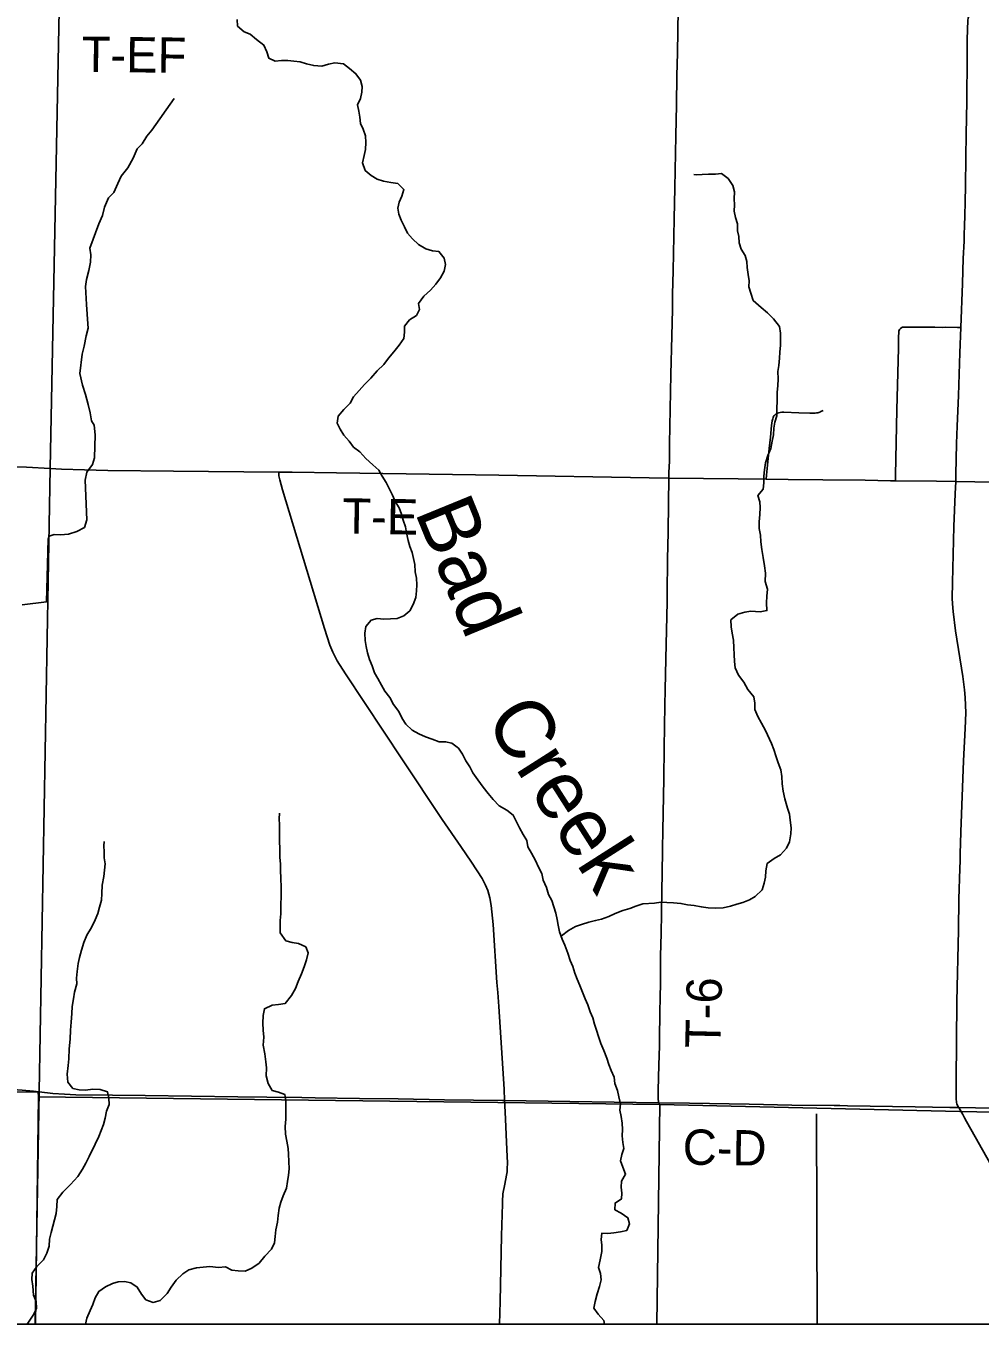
# Model space of a CAD drawing. Extents: x -21.7 to 34, y 0 to 22.
# Drawn here: x 27.584 to 29.12, y 14.1 to 16.19 of the extents above; entities that cross this region are included whole.
import ezdxf

# ---------------------------------------------------------------- set-up
doc = ezdxf.new("R2010")
doc.units = 0
for name, color, linetype in [('Default', 7, 'Continuous'), ('GM_X_County_Road', 7, 'Continuous'), ('GM_X_County_Road_Text', 7, 'Continuous'), ('GM_X_Interchange_Ramps', 7, 'Continuous'), ('GM_X_Minor_River', 7, 'Continuous'), ('GM_X_Minor_River_Text', 7, 'Continuous'), ('GM_X_Township_Road', 7, 'Continuous'), ('GM_X_Township_Road_Text', 7, 'Continuous'), ('SH_Data', 7, 'Continuous')]:
    doc.layers.add(name, color=color, linetype=linetype)

msp = doc.modelspace()

# ---------------------------------------------------------------- linework, layer by layer
at = {"layer": 'Default'}
for points in [[(26.5915, 14.1), (27.5993, 14.1), (27.6043, 14.466), (27.6038, 14.4739), (26.5986, 14.4731)], [(27.5993, 14.1), (28.6, 14.1), (28.6048, 14.4532), (27.6043, 14.466)], [(28.6, 14.1), (29.6028, 14.1), (29.6079, 14.4319), (29.0878, 14.4424), (28.6048, 14.4532)]]:
    msp.add_lwpolyline(points, close=True, dxfattribs=at)
at = {"layer": 'GM_X_County_Road'}
msp.add_line((29.0861, 14.4487), (29.1664, 14.4468), dxfattribs=at)
for points in [[(29.0896, 15.7041), (29.0923, 15.775), (29.0934, 15.8153), (29.0948, 15.8432), (29.0949, 15.8534), (29.0953, 15.8687), (29.0957, 15.8839), (29.0966, 15.9068), (29.097, 15.9317), (29.0975, 15.9781), (29.0981, 16.0154), (29.099, 16.0683), (29.0997, 16.1398), (29.0999, 16.1678), (29.1009, 16.1989), (29.1013, 16.2021), (29.1026, 16.2053), (29.1044, 16.2067)], [(29.0812, 15.4562), (29.0812, 15.4677), (29.0826, 15.5174), (29.0836, 15.5454), (29.0848, 15.5702), (29.0855, 15.5951), (29.0881, 15.6634), (29.0896, 15.7041)], [(27.4894, 15.481), (27.5228, 15.4808), (27.5477, 15.4805), (27.5851, 15.4792), (27.6231, 15.4773)], [(27.6231, 15.4773), (27.6411, 15.4764), (27.6785, 15.475), (27.7159, 15.4739), (27.8218, 15.4729), (27.9911, 15.4712)], [(28.3548, 14.4599), (28.3541, 14.4779), (28.3457, 14.6113), (28.3438, 14.6338), (28.3425, 14.65), (28.3363, 14.743), (28.3332, 14.7739), (28.3311, 14.786), (28.3277, 14.7978), (28.3242, 14.8064), (28.3184, 14.8172), (28.3015, 14.8433), (28.2841, 14.8689), (28.2542, 14.9124), (28.1905, 15.0082), (28.0985, 15.1465), (28.0853, 15.1676), (28.0781, 15.1815), (28.0734, 15.193), (28.0647, 15.2197), (27.9973, 15.4428), (27.9927, 15.4592), (27.9915, 15.4635), (27.9913, 15.4653), (27.9912, 15.4671), (27.9911, 15.4692), (27.9911, 15.4712)], [(29.0861, 14.4487), (29.0849, 14.4506), (29.0829, 14.4545), (29.0823, 14.4567), (29.0821, 14.4633), (29.0818, 14.4918), (29.0833, 14.6193), (29.0857, 14.7343), (29.0865, 14.7841), (29.0878, 14.8336), (29.0885, 14.8457), (29.0886, 14.8579), (29.0887, 14.8735), (29.0893, 14.8922), (29.0939, 15.0067), (29.0963, 15.059), (29.0973, 15.0838), (29.0972, 15.0962), (29.0967, 15.1086), (29.0955, 15.1209), (29.0926, 15.1425), (29.0811, 15.2162), (29.0772, 15.247), (29.076, 15.2594), (29.0757, 15.2688), (29.076, 15.2937), (29.0782, 15.3838), (29.0804, 15.4366), (29.0812, 15.4562)], [(27.355, 14.4777), (27.4534, 14.4782), (27.5404, 14.4786), (27.556, 14.4782), (27.5778, 14.4767), (27.5963, 14.4748), (27.6052, 14.4738)], [(27.6052, 14.4738), (27.6272, 14.4714), (27.6458, 14.4699), (27.6644, 14.4692), (27.7234, 14.4683), (27.7762, 14.4677), (27.9254, 14.4658), (27.972, 14.4655), (28.028, 14.4646), (28.0497, 14.464), (28.1212, 14.4632), (28.1833, 14.4623), (28.2579, 14.4611), (28.3512, 14.46), (28.3548, 14.4599)], [(28.3466, 14.1), (28.3474, 14.1363), (28.3496, 14.2418), (28.3512, 14.2936), (28.3515, 14.3009), (28.3518, 14.3058), (28.3522, 14.3095), (28.3552, 14.3252), (28.358, 14.3398), (28.3587, 14.3453), (28.359, 14.3505), (28.3592, 14.3591), (28.3586, 14.3808), (28.3555, 14.4417), (28.3548, 14.4599)], [(28.3548, 14.4599), (28.4598, 14.4582), (28.6024, 14.4561)], [(28.6024, 14.4561), (28.6524, 14.4554), (28.7487, 14.4538), (28.8171, 14.4526), (28.8854, 14.4518), (28.8947, 14.4516), (28.907, 14.4511), (29.0158, 14.4495), (29.0717, 14.4487), (29.0861, 14.4487)]]:
    msp.add_lwpolyline(points, dxfattribs=at)
at = {"layer": 'GM_X_Interchange_Ramps'}
for points in [[(23.5167, 14.1), (27.5987, 14.1), (27.605, 14.4744), (27.6229, 15.4779), (27.6372, 16.2146)], [(27.6372, 16.2146), (27.6229, 15.4779), (27.605, 14.4744), (27.5987, 14.1), (30.3167, 14.1)]]:
    msp.add_lwpolyline(points, dxfattribs=at)
at = {"layer": 'GM_X_Minor_River'}
msp.add_line((28.858, 14.1), (28.8568, 14.4386), dxfattribs=at)
for points in [[(28.0851, 15.5504), (28.0869, 15.5617), (28.0958, 15.5722), (28.1062, 15.5826), (28.1117, 15.5928), (28.1207, 15.6028), (28.1292, 15.6125), (28.1396, 15.623), (28.1497, 15.6345), (28.1601, 15.6449), (28.1679, 15.655), (28.1765, 15.6651), (28.185, 15.676), (28.1924, 15.6868), (28.1938, 15.697), (28.1936, 15.7065), (28.2014, 15.7166), (28.2129, 15.7236), (28.218, 15.7334), (28.2159, 15.7429), (28.2245, 15.7545), (28.2356, 15.7642), (28.2438, 15.7743), (28.2516, 15.7843), (28.2575, 15.7952), (28.2596, 15.8058), (28.2575, 15.8157), (28.249, 15.8265), (28.2388, 15.8275), (28.2279, 15.8308), (28.2163, 15.8382), (28.2062, 15.8468), (28.1985, 15.8564), (28.1934, 15.8664), (28.1883, 15.8771), (28.1843, 15.8867), (28.1826, 15.8962), (28.1851, 15.9061), (28.1894, 15.9158), (28.1927, 15.9264), (28.1826, 15.9361), (28.1717, 15.9375), (28.16, 15.94), (28.1498, 15.9432), (28.1401, 15.9491), (28.13, 15.9573), (28.1261, 15.9695), (28.1286, 15.9812), (28.1307, 15.9911), (28.1313, 16.0024), (28.1307, 16.0127), (28.1268, 16.0234), (28.1228, 16.033), (28.1219, 16.0429), (28.1202, 16.0524), (28.1181, 16.0627), (28.1228, 16.0729), (28.1249, 16.0831), (28.1255, 16.0925), (28.1227, 16.1025), (28.1153, 16.1129), (28.1049, 16.1214), (28.0952, 16.1288), (28.0816, 16.1306), (28.0713, 16.1282), (28.0606, 16.125), (28.0474, 16.126), (28.0357, 16.1289), (28.0255, 16.1318), (28.0153, 16.1331), (28.0055, 16.1344), (27.9956, 16.1343), (27.9854, 16.1333), (27.9752, 16.1377), (27.9717, 16.148), (27.9673, 16.1591), (27.9554, 16.1681), (27.945, 16.1767), (27.9352, 16.1803), (27.9248, 16.1896), (27.9242, 16.1999)], [(27.578, 15.2576), (27.6168, 15.2625), (27.6196, 15.3638), (27.6212, 15.3683), (27.6296, 15.3712), (27.6394, 15.3706), (27.6523, 15.3715), (27.666, 15.3758), (27.6783, 15.3824), (27.682, 15.3948), (27.6794, 15.4583), (27.682, 15.4715), (27.6913, 15.4839), (27.6946, 15.4945), (27.6953, 15.5313), (27.6937, 15.5473), (27.6893, 15.5542), (27.6873, 15.5671), (27.6842, 15.5801), (27.6799, 15.5965), (27.6753, 15.6114), (27.6708, 15.6301), (27.6744, 15.6612), (27.6777, 15.6744), (27.6807, 15.691), (27.684, 15.7031), (27.6834, 15.7104), (27.6817, 15.7411), (27.6796, 15.7704), (27.6814, 15.7818), (27.6854, 15.7961), (27.688, 15.8094), (27.6886, 15.8215), (27.6869, 15.8322), (27.7013, 15.8714), (27.7073, 15.8845), (27.7106, 15.8981), (27.717, 15.9132), (27.7255, 15.9218), (27.7322, 15.9364), (27.7374, 15.9481), (27.7482, 15.9612), (27.7565, 15.977), (27.7632, 15.992), (27.771, 16.0002), (27.7788, 16.0122), (27.7869, 16.0219), (27.8224, 16.0728)], [(28.7902, 15.5521), (28.793, 15.5619), (28.7932, 15.573), (28.7939, 15.5874), (28.7938, 15.6003), (28.7948, 15.6105), (28.7953, 15.6215), (28.7948, 15.6333), (28.7965, 15.6431), (28.7975, 15.6549), (28.7981, 15.6647), (28.7991, 15.6757), (28.7993, 15.6856), (28.7991, 15.6951), (28.7974, 15.7058), (28.7878, 15.7181), (28.7782, 15.7278), (28.7681, 15.7364), (28.7551, 15.748), (28.7511, 15.7595), (28.7483, 15.7698), (28.7485, 15.7797), (28.7468, 15.7896), (28.7455, 15.801), (28.745, 15.8105), (28.7421, 15.8204), (28.7355, 15.8304), (28.7323, 15.8407), (28.7321, 15.8506), (28.73, 15.8601), (28.7299, 15.8712), (28.7267, 15.8815), (28.7246, 15.8918), (28.7252, 15.902), (28.7246, 15.9115), (28.7248, 15.9225), (28.7224, 15.9328), (28.715, 15.944), (28.7042, 15.9522), (28.6943, 15.9509), (28.6834, 15.9511), (28.6727, 15.9505), (28.6633, 15.95), (28.6595, 15.9508)], [(28.4887, 14.6138), (28.4844, 14.6234), (28.48, 14.6341), (28.4761, 14.6449), (28.4714, 14.6552), (28.4681, 14.6651), (28.4649, 14.6755), (28.4602, 14.6854), (28.4567, 14.6973), (28.4516, 14.7099), (28.4473, 14.7195), (28.4433, 14.7313), (28.4413, 14.742), (28.4392, 14.7515), (28.4375, 14.7614), (28.4343, 14.7718), (28.4307, 14.7817), (28.4256, 14.7913), (28.4224, 14.8028), (28.417, 14.8146), (28.4145, 14.8253), (28.4094, 14.8353), (28.4044, 14.846), (28.3982, 14.8583), (28.3923, 14.8683), (28.3906, 14.8782), (28.3847, 14.8882), (28.3789, 14.8989), (28.3734, 14.9093), (28.3687, 14.9193), (28.3583, 14.9275), (28.3463, 14.9342), (28.3363, 14.9446), (28.3281, 14.9543), (28.3204, 14.9643), (28.3115, 14.9763), (28.3034, 14.9874), (28.299, 14.997), (28.2924, 15.0066), (28.287, 15.0174), (28.2803, 15.027), (28.2699, 15.0352), (28.2597, 15.0373), (28.2495, 15.0375), (28.2382, 15.0415), (28.2273, 15.0455), (28.2168, 15.0499), (28.2059, 15.0558), (28.1959, 15.0655), (28.19, 15.0751), (28.1842, 15.0859), (28.176, 15.0975), (28.1702, 15.1086), (28.1617, 15.119), (28.1566, 15.1286), (28.1507, 15.139), (28.1453, 15.1486), (28.1413, 15.1597), (28.1373, 15.1696), (28.1341, 15.1803), (28.1317, 15.191), (28.13, 15.2005), (28.1299, 15.2123), (28.1312, 15.2229), (28.1398, 15.233), (28.1497, 15.2358), (28.1602, 15.2348), (28.1712, 15.2354), (28.1819, 15.2359), (28.1926, 15.2399), (28.2022, 15.2484), (28.2077, 15.2582), (28.2117, 15.2699), (28.2131, 15.2805), (28.2136, 15.29), (28.2131, 15.301), (28.211, 15.3109), (28.2101, 15.3227), (28.2081, 15.3326), (28.206, 15.3421), (28.202, 15.3517), (28.1995, 15.3616), (28.1967, 15.3735), (28.1954, 15.3834), (28.1915, 15.3941), (28.1886, 15.404), (28.1851, 15.414), (28.1788, 15.4243), (28.1745, 15.4343), (28.1694, 15.4439), (28.1639, 15.455), (28.1577, 15.465), (28.1522, 15.4746), (28.1425, 15.4832), (28.1313, 15.4933), (28.1217, 15.5041), (28.1116, 15.5115), (28.1046, 15.5211), (28.0957, 15.5308), (28.0899, 15.5404), (28.0851, 15.5504)], [(28.4462, 14.7252), (28.4578, 14.7333), (28.4689, 14.7399), (28.4784, 14.7432), (28.4903, 14.7471), (28.5013, 14.7495), (28.5108, 14.752), (28.5226, 14.7563), (28.5326, 14.7611), (28.5452, 14.7657), (28.5566, 14.7689), (28.5662, 14.7725), (28.5772, 14.7765), (28.5962, 14.7776), (28.6064, 14.7789), (28.6163, 14.7787), (28.6269, 14.7781), (28.6386, 14.7771), (28.6495, 14.775), (28.6601, 14.7737), (28.6715, 14.7719), (28.6828, 14.7698), (28.6945, 14.7696), (28.707, 14.7701), (28.7185, 14.7729), (28.7287, 14.7757), (28.7386, 14.7785), (28.749, 14.7829), (28.7585, 14.7884), (28.7694, 14.7992), (28.7726, 14.8098), (28.7747, 14.8196), (28.7757, 14.8294), (28.7778, 14.8416), (28.7889, 14.8493), (28.7993, 14.8555), (28.809, 14.866), (28.8137, 14.8765), (28.8159, 14.889), (28.8165, 14.8989), (28.8144, 14.9111), (28.8135, 14.9206), (28.8106, 14.9305), (28.806, 14.9454), (28.8032, 14.958), (28.8016, 14.9698), (28.8011, 14.9816), (28.7994, 14.9922), (28.7951, 15.0033), (28.7922, 15.0133), (28.7883, 15.0247), (28.7847, 15.0347), (28.7749, 15.0554), (28.7687, 15.0673), (28.7625, 15.078), (28.7578, 15.0892), (28.7576, 15.0994), (28.7559, 15.1097), (28.7467, 15.1217), (28.7401, 15.1332), (28.7316, 15.1447), (28.7262, 15.1566), (28.7252, 15.1665), (28.7243, 15.1779), (28.7238, 15.1886), (28.7233, 15.2007), (28.7212, 15.2122), (28.7195, 15.2224), (28.719, 15.2335), (28.7302, 15.2427), (28.7416, 15.2459), (28.7515, 15.2476), (28.7662, 15.2466), (28.7773, 15.2486), (28.7764, 15.2608), (28.777, 15.2718), (28.7783, 15.2828), (28.7744, 15.2954), (28.7747, 15.309), (28.7734, 15.3208), (28.771, 15.3338), (28.769, 15.3471), (28.7674, 15.3593), (28.7668, 15.37), (28.7648, 15.3806), (28.765, 15.3916), (28.7656, 15.4034), (28.7662, 15.4144), (28.7656, 15.4239), (28.7628, 15.4338), (28.7713, 15.4439), (28.7723, 15.4545), (28.7725, 15.4648), (28.7731, 15.475), (28.7752, 15.4864), (28.7789, 15.4984), (28.7836, 15.5097), (28.7858, 15.5211), (28.7879, 15.5317), (28.7885, 15.5423), (28.7902, 15.5521)], [(27.9942, 14.7605), (27.9951, 14.8034), (27.9942, 14.8171), (27.9938, 14.8308), (27.994, 14.8402), (27.993, 14.8517), (27.9929, 14.8612), (27.9925, 14.8809), (27.9924, 14.8927), (27.9922, 14.9037), (27.9916, 14.9132), (27.9922, 14.9223)], [(27.5858, 14.1), (27.5881, 14.103), (27.5956, 14.1143), (27.6011, 14.1248), (27.6002, 14.1362), (27.5962, 14.1465), (27.595, 14.161), (27.5937, 14.1716), (27.5939, 14.1819), (27.6013, 14.1927), (27.6121, 14.2035), (27.6177, 14.2141), (27.6213, 14.2254), (27.6219, 14.2364), (27.6244, 14.2473), (27.6272, 14.2575), (27.6297, 14.2677), (27.6326, 14.2779), (27.6336, 14.2893), (27.6345, 14.3003), (27.6435, 14.3123), (27.6559, 14.3245), (27.6675, 14.3376), (27.6753, 14.3492), (27.6804, 14.359), (27.6859, 14.3695), (27.6954, 14.3898), (27.7014, 14.4019), (27.705, 14.4117), (27.709, 14.4214), (27.7118, 14.4316), (27.7139, 14.4426), (27.718, 14.4535), (27.7174, 14.4638), (27.7153, 14.4737), (27.7037, 14.4774), (27.6919, 14.478), (27.6798, 14.4767), (27.6696, 14.4773), (27.6597, 14.4794), (27.6512, 14.4894), (27.6504, 14.5024), (27.6522, 14.5164), (27.6528, 14.527), (27.6535, 14.5433), (27.6553, 14.5585), (27.6556, 14.5729), (27.6566, 14.5862), (27.6576, 14.5998), (27.6586, 14.6112), (27.6604, 14.6233), (27.6621, 14.6343), (27.6658, 14.6475), (27.6656, 14.657), (27.6666, 14.6676), (27.6683, 14.6805), (27.6704, 14.6903), (27.6733, 14.702), (27.677, 14.7145), (27.6821, 14.7258), (27.6896, 14.7385), (27.6955, 14.7509), (27.6995, 14.7611), (27.7024, 14.7709), (27.7056, 14.7823), (27.7062, 14.7933), (27.7069, 14.8065), (27.7094, 14.8205), (27.7104, 14.8308), (27.7114, 14.841), (27.71, 14.8505), (27.7099, 14.8604), (27.7093, 14.8699), (27.7098, 14.8767)], [(27.68, 14.1), (27.6818, 14.1095), (27.6874, 14.1219), (27.6918, 14.1317), (27.6954, 14.1422), (27.7016, 14.1524), (27.712, 14.1598), (27.7231, 14.1652), (27.7327, 14.1681), (27.7425, 14.1683), (27.7531, 14.1665), (27.7632, 14.1595), (27.7701, 14.1483), (27.7771, 14.1387), (27.7888, 14.1347), (27.7999, 14.1379), (27.8114, 14.149), (27.8177, 14.1595), (27.8259, 14.1708), (27.8367, 14.1808), (27.8463, 14.1871), (27.8585, 14.1906), (27.8695, 14.1915), (27.8801, 14.1928), (27.8941, 14.191), (27.9055, 14.1919), (27.9153, 14.1868), (27.9258, 14.1855), (27.9368, 14.1849), (27.9479, 14.1899), (27.9594, 14.1981), (27.9684, 14.2093), (27.9792, 14.2205), (27.9843, 14.2306), (27.9853, 14.2408), (27.9866, 14.2514), (27.9892, 14.2639), (27.9901, 14.2749), (27.9919, 14.2863), (27.9944, 14.2961), (27.9984, 14.3066), (28.0035, 14.3187), (28.0053, 14.3297), (28.007, 14.3399), (28.0076, 14.3501), (28.0071, 14.3619), (28.0069, 14.3733), (28.006, 14.3828), (28.0043, 14.3942), (28.0022, 14.4057), (28.0014, 14.4178), (28.0024, 14.4296), (28.0026, 14.4398), (28.0024, 14.4493), (28.0026, 14.46), (28.0009, 14.4695), (27.9907, 14.4735), (27.9806, 14.476), (27.974, 14.4875), (27.9708, 14.4997), (27.9714, 14.5126), (27.9705, 14.5221), (27.9685, 14.5351), (27.9661, 14.5488), (27.9668, 14.5617), (27.9658, 14.5731), (27.9657, 14.5845), (27.9659, 14.5966), (27.9681, 14.6076), (27.9803, 14.6134), (27.9909, 14.6144), (28.0016, 14.6161), (28.0117, 14.6288), (28.0183, 14.64), (28.0224, 14.6513), (28.0275, 14.6638), (28.0319, 14.6751), (28.0356, 14.6864), (28.0384, 14.6977), (28.0345, 14.7073), (28.0228, 14.7128), (28.0126, 14.7142), (28.0025, 14.7167), (27.9932, 14.7298), (27.9931, 14.7396), (27.9933, 14.7495), (27.9942, 14.7605)], [(28.5156, 14.1), (28.5145, 14.1056), (28.5056, 14.1157), (28.4986, 14.1253), (28.5007, 14.1363), (28.504, 14.1488), (28.5076, 14.1605), (28.5105, 14.1714), (28.5092, 14.1813), (28.506, 14.1912), (28.5088, 14.2033), (28.5114, 14.217), (28.5112, 14.2268), (28.5103, 14.2363), (28.5112, 14.2462), (28.5211, 14.246), (28.5306, 14.2466), (28.5412, 14.2483), (28.5515, 14.2507), (28.5559, 14.2612), (28.553, 14.2712), (28.5426, 14.2786), (28.5321, 14.2841), (28.5327, 14.2948), (28.543, 14.3014), (28.5436, 14.3109), (28.5423, 14.3204), (28.5428, 14.3299), (28.5495, 14.3411), (28.5452, 14.3526), (28.5416, 14.3625), (28.5437, 14.3728), (28.5466, 14.3826), (28.5452, 14.3921), (28.5443, 14.4031), (28.5449, 14.413), (28.5443, 14.4232), (28.5423, 14.4339), (28.5406, 14.4442), (28.5412, 14.4544), (28.5388, 14.4659), (28.5367, 14.4758), (28.5324, 14.4873), (28.5311, 14.4976), (28.5264, 14.5083), (28.5224, 14.5179), (28.5192, 14.5278), (28.5145, 14.5404), (28.5098, 14.5519), (28.5062, 14.563), (28.503, 14.5733), (28.4998, 14.5829), (28.497, 14.5928), (28.4926, 14.6028), (28.4887, 14.6138)]]:
    msp.add_lwpolyline(points, dxfattribs=at)
at = {"layer": 'GM_X_Township_Road'}
for points in [[(28.6193, 15.4619), (28.6194, 15.4707), (28.6201, 15.4889), (28.6201, 15.4983), (28.6206, 15.5168), (28.6219, 15.6006), (28.6226, 15.6285), (28.6241, 15.6907), (28.6254, 15.7334), (28.6252, 15.7458), (28.6254, 15.7582), (28.6262, 15.7955), (28.6281, 15.8794), (28.6291, 15.9292), (28.6306, 16.0131), (28.6317, 16.0628), (28.6323, 16.1095), (28.6333, 16.1467), (28.6345, 16.216)], [(28.9841, 15.4576), (28.9843, 15.4664), (28.9867, 15.572), (28.9889, 15.6709), (28.9893, 15.6899), (28.9895, 15.6955), (28.9899, 15.6984), (28.9909, 15.7012)], [(28.9909, 15.7012), (28.9922, 15.7028), (28.9944, 15.7043), (28.9952, 15.7047), (28.9978, 15.705), (29.011, 15.705), (29.0179, 15.7048), (29.0233, 15.7049), (29.0478, 15.7047), (29.0602, 15.7045), (29.0644, 15.7047), (29.0842, 15.7042), (29.0896, 15.7041)], [(28.7914, 15.5646), (28.793, 15.5656), (28.7945, 15.5665), (28.7964, 15.567), (28.7984, 15.5674), (28.8011, 15.5678), (28.8044, 15.5679), (28.8288, 15.567), (28.8466, 15.5663), (28.8515, 15.5662), (28.8546, 15.5664), (28.857, 15.5668), (28.8594, 15.5671), (28.8622, 15.568), (28.8643, 15.569), (28.8678, 15.5706)], [(28.7761, 15.46), (28.7767, 15.4664), (28.7807, 15.5097), (28.783, 15.5279), (28.7846, 15.5464), (28.785, 15.5501), (28.7855, 15.5539), (28.786, 15.5558), (28.7865, 15.5575), (28.7871, 15.5595), (28.7877, 15.5608), (28.7886, 15.562), (28.7898, 15.5632), (28.7914, 15.5646)], [(27.4894, 15.481), (27.5228, 15.4808), (27.5477, 15.4805), (27.5851, 15.4792), (27.6231, 15.4773)], [(27.6231, 15.4773), (27.6411, 15.4764), (27.6785, 15.475), (27.7159, 15.4739), (27.8218, 15.4729), (27.9911, 15.4712)], [(27.9911, 15.4712), (27.9975, 15.4712), (28.0127, 15.4712), (28.0842, 15.4706), (28.3453, 15.4666), (28.5877, 15.4623), (28.6193, 15.4619)], [(28.6024, 14.4561), (28.6023, 14.4641), (28.6022, 14.4673), (28.6023, 14.4765), (28.6029, 14.5169), (28.604, 14.548), (28.604, 14.5635), (28.6048, 14.597), (28.6046, 14.6032), (28.6049, 14.6093), (28.6052, 14.6187), (28.6053, 14.631), (28.6059, 14.6433), (28.606, 14.6526), (28.6058, 14.6611), (28.6061, 14.6766), (28.6061, 14.6921), (28.6068, 14.7294), (28.6073, 14.7604), (28.6082, 14.8008), (28.6084, 14.8226), (28.6091, 14.8661), (28.6097, 14.894), (28.611, 14.978), (28.6117, 15.0277), (28.613, 15.0961), (28.6136, 15.1209), (28.6147, 15.1707), (28.6167, 15.2629), (28.6168, 15.2754), (28.6173, 15.3313), (28.6182, 15.3748), (28.6187, 15.4215), (28.6193, 15.4619)], [(28.6193, 15.4619), (28.7307, 15.4606), (28.7761, 15.46)], [(28.7761, 15.46), (28.8116, 15.4595), (28.8675, 15.4589), (28.9357, 15.4585), (28.976, 15.4577), (28.9841, 15.4576)], [(28.9841, 15.4576), (29.0502, 15.4569), (29.0812, 15.4562)], [(29.0812, 15.4562), (29.1122, 15.4558), (29.1459, 15.4553), (29.6251, 15.4481)], [(29.2884, 14.1), (29.2697, 14.1303), (29.2442, 14.1729), (29.2257, 14.2051), (29.202, 14.2452), (29.1806, 14.2827), (29.1508, 14.3339), (29.1386, 14.3557), (29.0987, 14.4258), (29.0953, 14.4318), (29.0926, 14.4371), (29.0861, 14.4487)]]:
    msp.add_lwpolyline(points, dxfattribs=at)
at = {"layer": 'SH_Data'}
msp.add_line((23.5167, 14.1), (30.3167, 14.1), dxfattribs=at)
msp.add_lwpolyline([(23.5167, 20.9), (30.3167, 20.9), (30.3167, 14.1), (23.5167, 14.1)], close=True, dxfattribs=at)

# ---------------------------------------------------------------- texts
at = {"layer": 'GM_X_County_Road_Text'}
msp.add_text('C-D', height=0.05682, rotation=359.2081, dxfattribs=at).set_placement((28.6413, 14.3567))
at = {"layer": 'GM_X_Minor_River_Text'}
for s, height, rotation, p in [('Bad', 0.09477, 292.2535, (28.2094, 15.4078)), ('Creek', 0.09476, 302.4878, (28.3219, 15.0728))]:
    msp.add_text(s, height=height, rotation=rotation, dxfattribs=at).set_placement(p)
at = {"layer": 'GM_X_Township_Road_Text'}
for s, rotation, p in [('T-EF', 359.3573, (27.6733, 16.116)), ('T-E', 359.1191, (28.093, 15.3727)), ('T-6', 88.6255, (28.7023, 14.5437))]:
    msp.add_text(s, height=0.05682, rotation=rotation, dxfattribs=at).set_placement(p)

doc.saveas('drawing.dxf')
